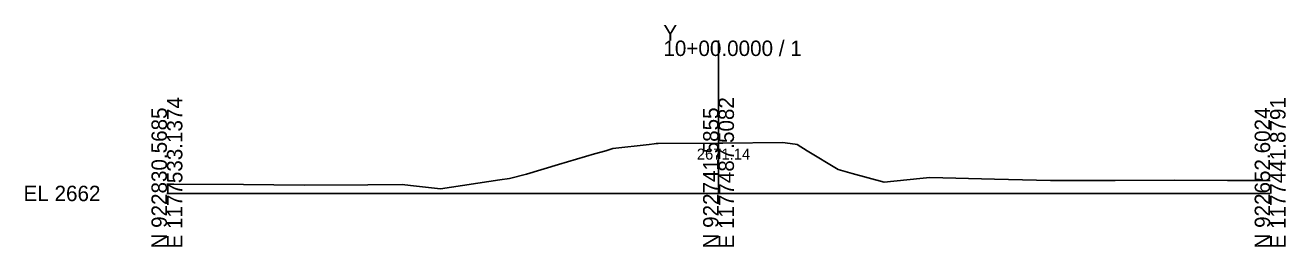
# Model space of a CAD drawing. Extents: x -26 to 203, y -10 to 2034.
# Drawn here: x -25.7 to 202.8, y -9.7 to 30.5 of the extents above; entities that cross this region are included whole.
import ezdxf

# ---------------------------------------------------------------- set-up
doc = ezdxf.new("R2010")
doc.units = 0
for name, color, linetype in [('Exist Cross Section Cell', 7, 'Continuous'), ('Exist XS Center Line Elevation Label', 7, 'Continuous'), ('Exist XS Ground Line', 7, 'Continuous')]:
    doc.layers.add(name, color=color, linetype=linetype)

msp = doc.modelspace()

# ---------------------------------------------------------------- linework, layer by layer
at = {"layer": 'Exist Cross Section Cell'}
for p, q in [((100, 0), (100, 27.75)), ((0, 0), (100, 0)), ((100, 0), (200, 0))]:
    msp.add_line(p, q, dxfattribs=at)
at = {"layer": 'Exist XS Ground Line'}
for p, q in [((89.05, 9.06), (100.14, 9.14)), ((100.14, 9.14), (100.77, 9.15)), ((100.77, 9.15), (111.61, 9.25)), ((111.61, 9.25), (113.88, 8.95)), ((71, 5.26), (77.54, 7.18)), ((77.54, 7.18), (79.55, 7.73)), ((79.55, 7.73), (80.82, 8.16)), ((80.82, 8.16), (87.4, 8.91)), ((87.4, 8.91), (88.35, 9.02)), ((88.35, 9.02), (88.7, 9.06)), ((88.7, 9.06), (89.05, 9.06)), ((113.88, 8.95), (114.23, 8.89)), ((114.23, 8.89), (116.08, 7.76)), ((116.08, 7.76), (121.68, 4.33)), ((65.16, 3.5), (71, 5.26)), ((49.62, 0.81), (60.34, 2.45)), ((60.34, 2.45), (62.13, 2.69)), ((62.13, 2.69), (65.16, 3.5)), ((121.68, 4.33), (124.23, 3.62)), ((124.23, 3.62), (130, 2.05)), ((130, 2.05), (136.49, 2.71)), ((136.49, 2.71), (138.3, 2.88)), ((138.3, 2.88), (150.05, 2.6)), ((150.05, 2.6), (160.16, 2.33)), ((160.16, 2.33), (171.9, 2.35)), ((171.9, 2.35), (182.72, 2.41)), ((182.72, 2.41), (192.27, 2.36)), ((192.27, 2.36), (200, 2.34)), ((0, 1.7), (1.27, 1.69)), ((1.27, 1.69), (13.87, 1.61)), ((13.87, 1.61), (24.85, 1.5)), ((24.85, 1.5), (36.4, 1.56)), ((36.4, 1.56), (42.64, 1.61)), ((42.64, 1.61), (44.13, 1.44)), ((44.13, 1.44), (49.62, 0.81))]:
    msp.add_line(p, q, dxfattribs=at)

# ---------------------------------------------------------------- texts
at = {"layer": 'Exist Cross Section Cell'}
for s, p in [('Y', (90, 27.75)), ('10+00.0000 / 1', (90, 24.95)), ('EL 2662', (-26, -1.4))]:
    msp.add_text(s, height=2.8, dxfattribs=at).set_placement(p)
for s, p in [('E 1177533.1374', (2.8, -10)), ('E 1177487.5082', (102.8, -10)), ('E 1177441.8791', (202.8, -10)), ('N 922830.5685', (0, -10)), ('N 922741.5855', (100, -10)), ('N 922652.6024', (200, -10))]:
    msp.add_text(s, height=2.8, rotation=90, dxfattribs=at).set_placement(p)
at = {"layer": 'Exist XS Center Line Elevation Label'}
msp.add_text('2671.14', height=2, dxfattribs=at).set_placement((96.07, 6.14))

doc.saveas('drawing.dxf')
